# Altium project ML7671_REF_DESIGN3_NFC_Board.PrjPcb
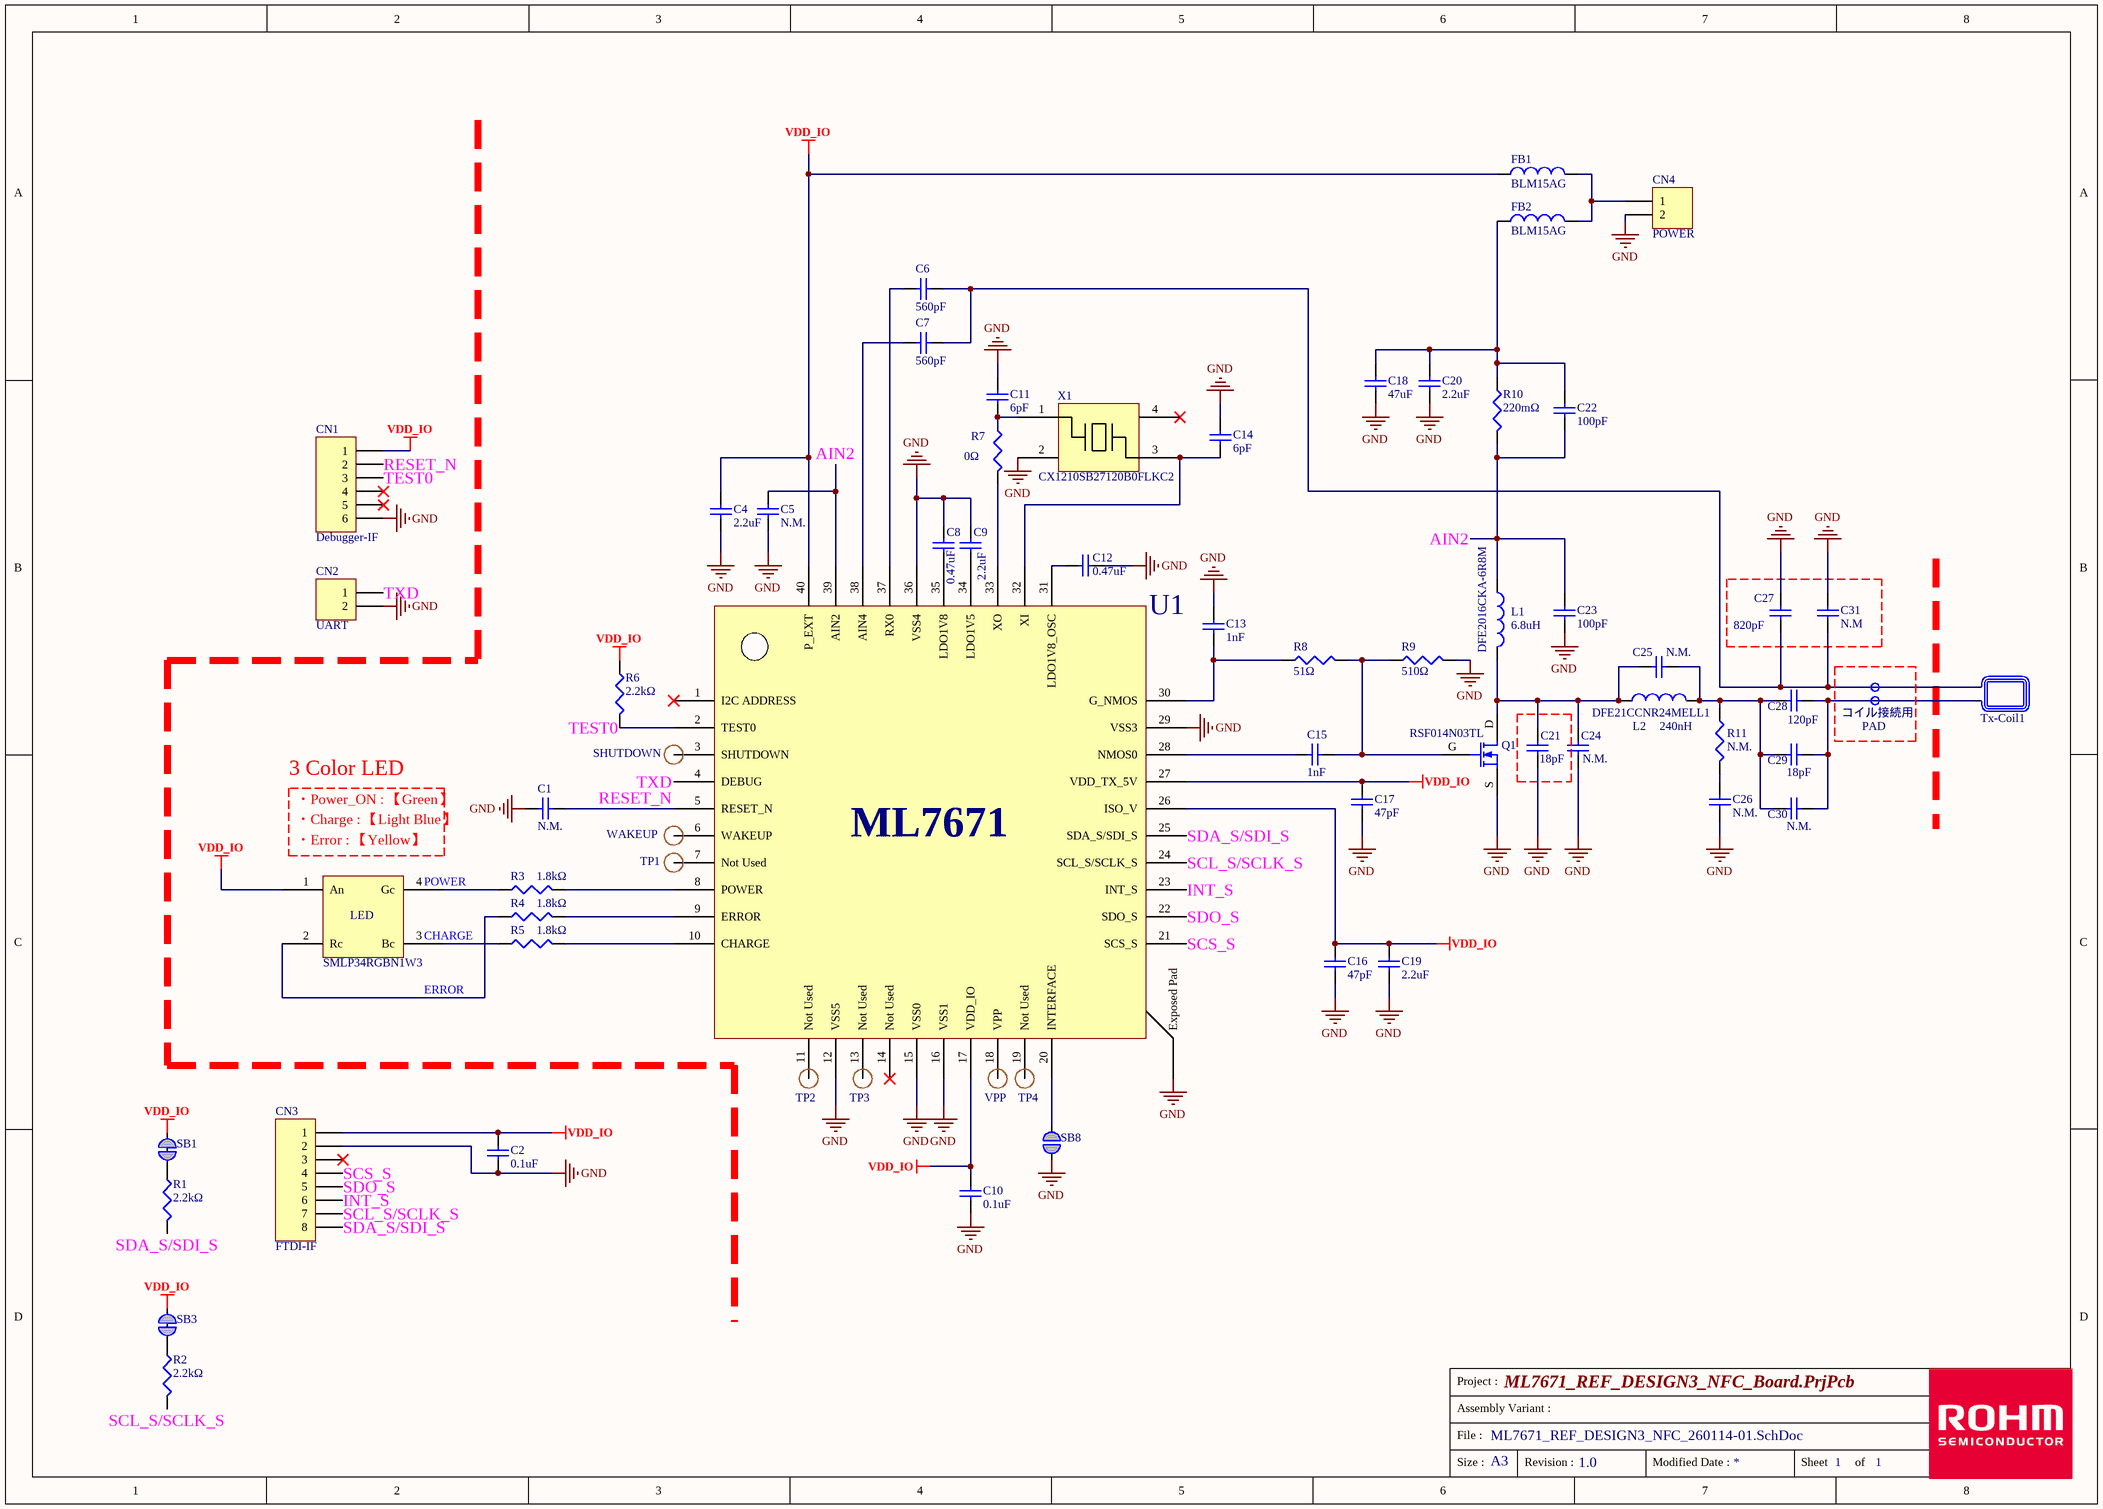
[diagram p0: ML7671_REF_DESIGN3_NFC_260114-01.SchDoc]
1 sheet, 64 parts. Net scope: global (net labels, ports and power ports of the same name join across sheets).
Board files: ML7671_REF_D3_NFC_final.PcbDoc, ML767X_REF_D3_NFC_panel.PcbDoc, ML767x_TP.PcbDoc

## Sheet ML7671_REF_DESIGN3_NFC_260114-01.SchDoc: ML7801_TX_Board
size A3; Revision: 1.0; SheetNumber: 1; SheetTotal: 1; Application: NFC TX

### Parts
C1  value N.M.  [0603-1_00]  (hidden comment: Cap)
C2  value 0.1uF  [0603-1_00]  (hidden comment: Cap)
C4  value 2.2uF  [0603-1_00]  (hidden comment: Cap)
C5  value N.M.  [0603-1_00]  (hidden comment: Cap)
C6  value 560pF  [0603-1_00]  (hidden comment: Cap)
C7  value 560pF  [0603-1_00]  (hidden comment: Cap)
C8  value 0.47uF  [0603-1_00]  (hidden comment: Cap)
C9  value 2.2uF  [0603-1_00]  (hidden comment: Cap)
C10  value 0.1uF  [0603-1_00]  (hidden comment: Cap)
C11  value 6pF  [0603-1_00]  (hidden comment: Cap)
C12  value 0.47uF  [0603-1_00]  (hidden comment: Cap)
C13  value 1nF  [0603-1_00]  (hidden comment: Cap)
C14  value 6pF  [0603-1_00]  (hidden comment: Cap)
C15  value 1nF  [0603-1_00]  (hidden comment: Cap)
C16  value 47pF  [0603-1_00]  (hidden comment: Cap)
C17  value 47pF  [0603-1_00]  (hidden comment: Cap)
C18  value 47uF  [GCM21_2125_00]  (hidden comment: Cap)
C19  value 2.2uF  [0603-1_00]  (hidden comment: Cap)
C20  value 2.2uF  [0603-1_00]  (hidden comment: Cap)
C21  value 18pF  [CC1005_02]  (hidden comment: Cap)
C22  value 100pF  [0603-1_00]  (hidden comment: Cap)
C23  value 100pF  [0603-1_00]  (hidden comment: Cap)
C24  value N.M.  [CC1005_02]  (hidden comment: Cap)
C25  N.M.  [CC1005_02]
C26  N.M.  [CC1005_02]
C27  value 820pF  [CC1005_02]  (hidden comment: Cap)
C28  value 120pF  [CC1005_02]  (hidden comment: Cap)
C29  value 18pF  [CC1005_02]  (hidden comment: Cap)
C30  value N.M.  [CC1005_02]  (hidden comment: Cap)
C31  value N.M  [CC1608_00]  (hidden comment: Cap)
CN1  Note: Debugger-IF  [CN6_XB-1-5]  (hidden comment: MHDR1X6)
CN2  Note: UART  [JP2-2.54_01]  (hidden comment: Header 2)
CN3  Note: FTDI-IF  [JP8-2.54_01]  (hidden comment: Header 8)
CN4  Note: POWER  [JP2-2.0_C0.8]  (hidden comment: Header 2)
FB1  BLM15AG  [CC1005_02]
FB2  BLM15AG  [CC1005_02]
L1  DFE2016CKA-6R8M  value 6.8uH  [L_2_2016_t065]
L2  DFE21CCNR24MELL1  value 240nH  [L_2_2012_t08]
LED  SMLP34RGBN1W3  [SMLP34RGB_00]
Q1  RSF014N03TL  [MMP_3_2120_TUMT_GSD]
R1  2.2kΩ  [RR1005_02]
R2  2.2kΩ  [RR1005_02]
R3  1.8kΩ  [RR1005_02]
R4  1.8kΩ  [RR1005_02]
R5  1.8kΩ  [RR1005_02]
R6  2.2kΩ  [RR1005_02]
R7  0Ω  [RR1005_02]
R8  51Ω  [RR1005_02]
R9  510Ω  [RR1005_02]
R10  220mΩ  [LTR10_00]
R11  N.M.  [RR1005_02]
SB1  Solderbridge Shorted  [Solderbridge_Shorted_Power]  (value not drawn)
SB3  Solderbridge Shorted  [Solderbridge_Shorted_Power]  (value not drawn)
SB8  Solderbridge  [Solderbridge]  (value not drawn)
SHUTDOWN  (no value)  [TP_PAD0.5_01]
TP1  (no value)  [TP_PAD0.5_01]
TP2  (no value)  [TP_PAD0.5_01]
TP3  (no value)  [TP_PAD0.5_01]
TP4  (no value)  [TP_PAD0.5_01]
Tx-Coil1  -  [Tx-Coil1]  (value not drawn)
U1  -  [QFN50P600X600X80_41N_ROHM]  (value not drawn)
VPP  (no value)  [TP_PAD0.5_01]
WAKEUP  (no value)  [TP_PAD0.5_01]
X1  CX1210SB27120B0FLKC2  [X_4_1210_0.52x0.45]

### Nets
GND: C1.2 C2.2 C4.2 C5.2 C8.1 C9.1 C10.2 C11.1 C12.2 C13.2 C14.1 C16.2 C17.2 C18.2 C19.2 C20.2 C21.2 C23.2 C24.2 C26.2 C27.1 C31.1 CN1.6 CN2.2 CN3.2 CN4.2 Q1.S R9.1 SB8.1 U1.12(VSS5) U1.15(VSS0) U1.16(VSS1) U1.29(VSS3) U1.36(VSS4) U1.41(Exposed_Pad) X1.2
VDD_IO: C2.1 C4.1 C10.1 C16.1 C17.1 C19.1 CN1.1 CN3.1 FB1.1 LED.1(An) R6.2 SB1.1 SB3.1 U1.17(VDD_IO) U1.26(ISO_V) U1.27(VDD_TX_5V) U1.40(P_EXT)
AIN2: C5.1 C22.2 C23.1 L1.2 R10.2 U1.39(AIN2)
INT_S: CN3.6 U1.23(INT_S)
RESET_N: C1.1 CN1.2 U1.5(RESET_N)
SCL_S/SCLK_S: CN3.7 R2.1 U1.24(SCL_S/SCLK_S)
SCS_S: CN3.4 U1.21(SCS_S)
SDA_S/SDI_S: CN3.8 R1.1 U1.25(SDA_S/SDI_S)
SDO_S: CN3.5 U1.22(SDO_S)
TEST0: CN1.3 R6.1 U1.2(TEST0)
TXD: CN2.1 U1.4(DEBUG)
NetC6_1: C6.1 U1.37(RX0)
NetC6_2: C6.2 C7.2 C27.2 C31.2 Tx-Coil1.2
NetC7_1: C7.1 U1.38(AIN4)
NetC8_2: C8.2 U1.35(LDO1V8)
NetC9_2: C9.2 U1.34(LDO1V5)
NetC11_2: C11.2 R7.2 X1.1
NetC12_1: C12.1 U1.31(LDO1V8_OSC)
NetC13_1: C13.1 R8.2 U1.30(G_NMOS)
NetC14_2: C14.2 U1.32(XI) X1.3
NetC15_1: C15.1 U1.28(NMOS0)
NetC15_2: C15.2 Q1.G R8.1 R9.2
NetC18_1: C18.1 C20.1 C22.1 FB2.1 R10.1
NetC21_1: C21.1 C24.1 C25.1 L1.1 L2.2 Q1.D
NetC25_2: C25.2 C28.1 C29.1 C30.1 L2.1 R11.2
NetC26_1: C26.1 R11.1
NetC28_2: C28.2 C29.2 C30.2 Tx-Coil1.1
NetCN4_1: CN4.1 FB1.2 FB2.2
NetLED_2: LED.2(Rc) R4.2
NetLED_3: LED.3(Bc) R5.2
NetLED_4: LED.4(Gc) R3.2
NetR1_2: R1.2 SB1.2
NetR2_2: R2.2 SB3.2
NetR3_1: R3.1 U1.8(POWER)
NetR4_1: R4.1 U1.9(ERROR)
NetR5_1: R5.1 U1.10(CHARGE)
NetR7_1: R7.1 U1.33(XO)
NetSB8_2: SB8.2 U1.20(INTERFACE)
NetSHUTDOWN_1: SHUTDOWN.1 U1.3(SHUTDOWN)
NetTP1_1: TP1.1 U1.7(Not_Used)
NetTP2_1: TP2.1 U1.11(Not_Used)
NetTP3_1: TP3.1 U1.13(Not_Used)
NetTP4_1: TP4.1 U1.19(Not_Used)
NetU1_6: U1.6(WAKEUP) WAKEUP.1
NetU1_18: U1.18(VPP) VPP.1

Not connected (* = marked no-connect by the designer): CN1 4* 5*; CN3 3*; U1 1(I2C_ADDRESS)* 14(Not_Used)*; X1 4*

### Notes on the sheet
- コイル接続用
- 3 Color LED
- PAD
- ・Power_ON : 【Green】
- ・Charge : 【Light Blue】
- (near LED) ・Error : 【Yellow】
- (near LED) POWER
- (near LED) CHARGE
- ERROR

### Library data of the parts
C1 C5 C25 C26 C30 = Cap: Capacitor
C2 C10 = Cap: Capacitor; Part Number: GRM033R61C104KE18#; Note: 16Vdc,10%; Maker: Murata
C4 C9 C19 C20 = Cap: Capacitor; Part Number: GRM035R61C225ME01#; Note: 16Vdc,20%; Maker: Murata
C6 C7 = Cap: Capacitor; Part Number: GRM033R71C561KA01#; Note: 16Vdc,10%; Maker: Murata
C8 C12 = Cap: Capacitor; Part Number: GRM033R60J474KE90#; Note: 6.3Vdc,10%; Maker: Murata
C11 C14 = Cap: Capacitor; Part Number: GRM0335C1H100FA01#; Note: 50Vdc,1%; Maker: Murata
C13 = Cap: Capacitor; Part Number: GRM033B11E102KA01#; Note: 25Vdc,10%; Maker: Murata
C15 = Cap: Capacitor; Part Number: GRM0335C1E102FA01#; Note: 25Vdc,1%; Maker: Murata
C16 C17 = Cap: Capacitor; Part Number: GRM0335C1H470FA01#; Note: 50Vdc,1%; Maker: Murata
C18 = Cap: Capacitor; Part Number: GRM21BR61A476ME15#; Note: 10Vdc,20%; Maker: Murata
C21 = Cap: Capacitor; Part Number: GCM1555C1H121FA16#; Note: 50Vdc,1%,matching; Maker: Murata
C22 C23 = Cap: Capacitor; Part Number: GRM0335C1H101FA01#; Note: 50Vdc,1%; Maker: Murata
C24 = Cap: Capacitor; Note: matching
C27 = Cap: Capacitor; Part Number: GRM1555C1H391FA01#; Note: 50Vdc,1%,matching; Maker: Murata
C28 = Cap: Capacitor; Part Number: GRM1555C2A121GE01#; Note: 200Vdc,1%,matching; Maker: KEMET
C29 = Cap: Capacitor; Part Number: GQM1555C2D120FB01D; Note: 200Vdc,1%,matching; Maker: Murata
C31 = Cap: Capacitor; Part Number: GCM1885C1H222GA16#; Note: 50Vdc,2%,matching; Maker: Murata
CN1 = MHDR1X6: Header, 6-Pin; Part Number: XB-1-5-6P; Value: 6-Pin Header
CN2 = Header 2: Header, 2-Pin; Part Number: PH-1x2SG; Value: 2-Pin Header
CN3 = Header 8: Header, 8-Pin; Part Number: PH-1x8SG; Value: 8-Pin Header
CN4 = Header 2: Header, 2-Pin; Part Number: PH2-1X2SBG; Value: 2-Pin Header
FB1 FB2 = Inductor: Part Number: BLM15AG100SN1D; Maker: Murata
L1 = Inductor: Part Number: DFE2016CTC-4R7M; Maker: Murata
L2 = Inductor: Part Number: LQM2MPNR24MEHL; Maker: Murata
LED = RGB_LED: RGB LED; Note: 3-color LED; Maker: Rohm
Q1 = MOSFET-N: N-Channel MOSFET; Part Number: RQ5E035BN; Maker: Rohm
R1 R2 R6 = Res3: Resistor; Part Number: MCR01MZPJ222; Maker: Rohm; Note: 0.05W,±5%, Pull-up
R3-R5 = Res3: Resistor; Part Number: MCR01MZPJ182; Maker: Rohm
R7 = Res3: Resistor; Part Number: PMR01HZPJ000; Maker: Rohm
R8 = Res3: Resistor; Part Number: MCR01MZPJ510; Maker: Rohm; Note: 0.1W,±5%
R9 = Res3: Resistor; Part Number: MCR01MZPJ511; Maker: Rohm; Note: 0.1W,±5%
R10 = Res3: Resistor; Part Number: LTR10LEZPFLR220; Maker: Rohm; Note: 1W,±1%
R11 = Res3: Resistor
SB1 SB3 = SOLDERBRIDGE_SHORTED: Shorted Solderbridge
SHUTDOWN TP1-TP4 VPP WAKEUP = TP: Value: Small Pad
Tx-Coil1 = NFC_Antenna: NFC Antenna; Part Number: 「S24-T6」
U1 = ML7663: NFC TX, WQFN40; Part Number: ML7671; Maker: Rohm; Note: WQFN-40pin
X1 = SMD_Crystal: SMD Crystal; Maker: Kyocera

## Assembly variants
Variant of ML7671_REF_DESIGN3_NFC_Board: not fitted C1 C5 C17 C19 C20 C24 C25 C26 C30 CN1 R11 SB1 SB3 SB8 SHUTDOWN TP1 TP2 TP3 TP4 Tx-Coil1 VPP WAKEUP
